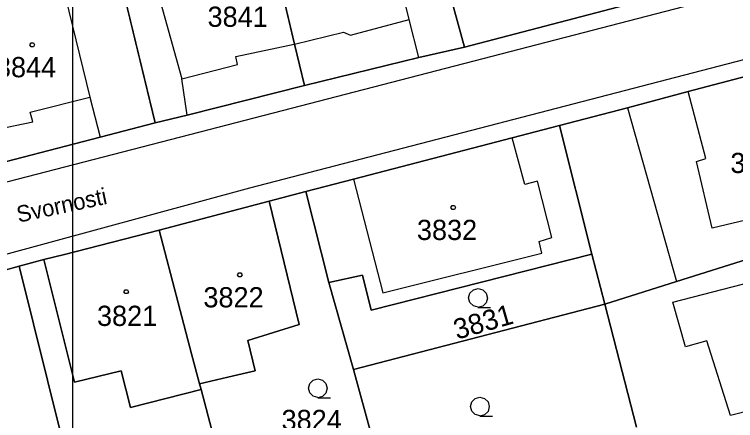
# Model space of a CAD drawing. Extents: x -263587 to -261993, y -1238795 to -1236748.
# Drawn here: x -262699.6 to -262642.6, y -1238145.4 to -1238113.2 of the extents above; entities that cross this region are included whole.
import ezdxf

# ---------------------------------------------------------------- set-up
doc = ezdxf.new("R2010")
doc.units = 0
doc.layers.add('Vrstva 1', color=7, linetype='Continuous')
doc.layers.add('Vrstva 51', color=7, linetype='Continuous')

msp = doc.modelspace()

# ---------------------------------------------------------------- linework, layer by layer
at = {"layer": 'Vrstva 1'}
for p, q in [((-262667.65, -1238102.68), (-262664.03, -1238115.82)), ((-262664.03, -1238115.82), (-262667.65, -1238102.68)), ((-262668.4, -1238113.62), (-262670.37, -1238105.54)), ((-262679.59, -1238106.68), (-262677.47, -1238115.57)), ((-262677.47, -1238115.57), (-262679.59, -1238106.68)), ((-262639.75, -1238109.44), (-262664.03, -1238115.82)), ((-262664.03, -1238115.82), (-262639.75, -1238109.44)), ((-262696.04, -1238109.96), (-262693.65, -1238119.78)), ((-262688.75, -1238109.85), (-262686.39, -1238118.33)), ((-262691.22, -1238110.44), (-262688.49, -1238121.81)), ((-262688.49, -1238121.81), (-262691.22, -1238110.44)), ((-262639.39, -1238110.71), (-262684.26, -1238122.35)), ((-262673.04, -1238114.87), (-262668.4, -1238113.62)), ((-262667.64, -1238116.63), (-262668.4, -1238113.62)), ((-262677.47, -1238115.57), (-262673.61, -1238114.64)), ((-262673.61, -1238114.64), (-262673.04, -1238114.87)), ((-262682.12, -1238116.57), (-262677.49, -1238115.57)), ((-262681.02, -1238126.95), (-262637.94, -1238115.76)), ((-262677.49, -1238115.57), (-262677.47, -1238115.57)), ((-262677.47, -1238115.57), (-262676.68, -1238118.85)), ((-262676.68, -1238118.85), (-262677.47, -1238115.57)), ((-262664.03, -1238115.82), (-262667.64, -1238116.63)), ((-262667.64, -1238116.63), (-262664.03, -1238115.82)), ((-262681.98, -1238117.19), (-262682.12, -1238116.57)), ((-262667.64, -1238116.63), (-262676.68, -1238118.85)), ((-262676.68, -1238118.85), (-262667.64, -1238116.63)), ((-262646.35, -1238119.34), (-262637.56, -1238117.01)), ((-262637.56, -1238117.01), (-262646.35, -1238119.34)), ((-262686.39, -1238118.33), (-262681.98, -1238117.19)), ((-262685.95, -1238121.19), (-262686.39, -1238118.33)), ((-262676.68, -1238118.85), (-262685.95, -1238121.19)), ((-262685.95, -1238121.19), (-262676.68, -1238118.85)), ((-262651.15, -1238120.61), (-262646.35, -1238119.34)), ((-262646.35, -1238119.34), (-262651.15, -1238120.61)), ((-262644.95, -1238124.63), (-262646.35, -1238119.34)), ((-262698.36, -1238120.95), (-262693.65, -1238119.78)), ((-262693.65, -1238119.78), (-262692.84, -1238122.94)), ((-262698.17, -1238121.72), (-262698.36, -1238120.95)), ((-262656.54, -1238122.03), (-262651.15, -1238120.61)), ((-262651.15, -1238120.61), (-262656.54, -1238122.03)), ((-262651.15, -1238120.61), (-262647.28, -1238134.37)), ((-262702.3, -1238122.58), (-262698.17, -1238121.72)), ((-262685.95, -1238121.19), (-262688.49, -1238121.81)), ((-262688.49, -1238121.81), (-262685.95, -1238121.19)), ((-262688.49, -1238121.81), (-262692.84, -1238122.94)), ((-262692.84, -1238122.94), (-262688.49, -1238121.81)), ((-262660.27, -1238123), (-262656.54, -1238122.03)), ((-262656.54, -1238122.03), (-262660.27, -1238123)), ((-262656.54, -1238122.03), (-262653.97, -1238132.2)), ((-262653.97, -1238132.2), (-262656.54, -1238122.03)), ((-262684.26, -1238122.35), (-262711.68, -1238129.45)), ((-262692.84, -1238122.94), (-262701.59, -1238125.22)), ((-262701.59, -1238125.22), (-262692.84, -1238122.94)), ((-262672.8, -1238126.27), (-262660.27, -1238123)), ((-262660.27, -1238123), (-262672.8, -1238126.27)), ((-262659.26, -1238126.68), (-262660.27, -1238123)), ((-262645.69, -1238124.86), (-262644.95, -1238124.63)), ((-262644.45, -1238130.14), (-262645.69, -1238124.86)), ((-262676.58, -1238127.25), (-262672.8, -1238126.27)), ((-262672.8, -1238126.27), (-262676.58, -1238127.25)), ((-262672.8, -1238126.27), (-262670.5, -1238135.27)), ((-262658.28, -1238126.42), (-262659.26, -1238126.68)), ((-262657.14, -1238130.89), (-262658.28, -1238126.42)), ((-262715.02, -1238136.22), (-262681.02, -1238126.95)), ((-262676.58, -1238127.25), (-262679.48, -1238128)), ((-262679.48, -1238128), (-262676.58, -1238127.25)), ((-262674.77, -1238134.44), (-262676.58, -1238127.25)), ((-262676.58, -1238127.25), (-262674.77, -1238134.44)), ((-262679.48, -1238128), (-262688.17, -1238130.3)), ((-262688.17, -1238130.3), (-262679.48, -1238128)), ((-262677.11, -1238137.76), (-262679.48, -1238128)), ((-262679.48, -1238128), (-262677.11, -1238137.76)), ((-262635.72, -1238128.03), (-262644.45, -1238130.14)), ((-262632.98, -1238129.87), (-262647.28, -1238134.37)), ((-262647.28, -1238134.37), (-262632.98, -1238129.87)), ((-262688.17, -1238130.3), (-262695.65, -1238132.22)), ((-262695.65, -1238132.22), (-262688.17, -1238130.3)), ((-262688.17, -1238130.3), (-262686.67, -1238136.06)), ((-262686.67, -1238136.06), (-262688.17, -1238130.3)), ((-262658.13, -1238131.19), (-262657.14, -1238130.89)), ((-262657.92, -1238132.11), (-262658.13, -1238131.19)), ((-262695.65, -1238132.22), (-262697.28, -1238132.63)), ((-262697.28, -1238132.63), (-262695.65, -1238132.22)), ((-262653.97, -1238132.2), (-262671.41, -1238136.62)), ((-262671.41, -1238136.62), (-262653.97, -1238132.2)), ((-262670.5, -1238135.27), (-262657.92, -1238132.11)), ((-262653.97, -1238132.2), (-262652.95, -1238136.16)), ((-262652.95, -1238136.16), (-262653.97, -1238132.2)), ((-262697.28, -1238132.63), (-262699.25, -1238133.16)), ((-262699.25, -1238133.16), (-262697.28, -1238132.63)), ((-262697.28, -1238132.63), (-262694.87, -1238142.34)), ((-262694.87, -1238142.34), (-262697.28, -1238132.63)), ((-262647.58, -1238136.01), (-262634.71, -1238132.65)), ((-262702.22, -1238133.98), (-262699.25, -1238133.16)), ((-262699.25, -1238133.16), (-262702.22, -1238133.98)), ((-262699.25, -1238133.16), (-262695.66, -1238147.61)), ((-262695.66, -1238147.61), (-262699.25, -1238133.16)), ((-262672.11, -1238133.86), (-262674.77, -1238134.44)), ((-262674.77, -1238134.44), (-262672.11, -1238133.86)), ((-262671.41, -1238136.62), (-262672.11, -1238133.86)), ((-262672.11, -1238133.86), (-262671.41, -1238136.62)), ((-262672.81, -1238141.32), (-262674.77, -1238134.44)), ((-262674.77, -1238134.44), (-262672.81, -1238141.32)), ((-262647.28, -1238134.37), (-262652.95, -1238136.16)), ((-262652.95, -1238136.16), (-262647.28, -1238134.37)), ((-262686.67, -1238136.06), (-262685.62, -1238140.09)), ((-262685.62, -1238140.09), (-262686.67, -1238136.06)), ((-262652.95, -1238136.16), (-262672.81, -1238141.32)), ((-262672.81, -1238141.32), (-262652.95, -1238136.16)), ((-262652.95, -1238136.16), (-262650.43, -1238145.89)), ((-262650.43, -1238145.89), (-262652.95, -1238136.16)), ((-262646.57, -1238139.53), (-262647.58, -1238136.01)), ((-262681.17, -1238139.02), (-262677.11, -1238137.76)), ((-262677.11, -1238137.76), (-262681.17, -1238139.02)), ((-262680.58, -1238141.42), (-262681.17, -1238139.02)), ((-262681.17, -1238139.02), (-262680.58, -1238141.42)), ((-262644.89, -1238139.05), (-262646.57, -1238139.53)), ((-262643, -1238144.96), (-262644.89, -1238139.05)), ((-262685.62, -1238140.09), (-262684.99, -1238142.45)), ((-262684.99, -1238142.45), (-262685.62, -1238140.09)), ((-262694.87, -1238142.34), (-262691.19, -1238141.44)), ((-262691.19, -1238141.44), (-262694.87, -1238142.34)), ((-262691.19, -1238141.44), (-262690.45, -1238144.33)), ((-262690.45, -1238144.33), (-262691.19, -1238141.44)), ((-262682.29, -1238141.82), (-262680.58, -1238141.42)), ((-262680.58, -1238141.42), (-262682.29, -1238141.82)), ((-262670.75, -1238148.86), (-262672.81, -1238141.32)), ((-262672.81, -1238141.32), (-262670.75, -1238148.86)), ((-262684.99, -1238142.45), (-262682.29, -1238141.82)), ((-262682.29, -1238141.82), (-262684.99, -1238142.45)), ((-262632.61, -1238142.25), (-262643, -1238144.96)), ((-262684.99, -1238142.45), (-262684.86, -1238142.92)), ((-262684.86, -1238142.92), (-262684.99, -1238142.45)), ((-262690.45, -1238144.33), (-262684.86, -1238142.92)), ((-262684.86, -1238142.92), (-262690.45, -1238144.33)), ((-262684.86, -1238142.92), (-262683.9, -1238146.52)), ((-262683.9, -1238146.52), (-262684.86, -1238142.92))]:
    msp.add_line(p, q, dxfattribs=at)
for points in [[(-262698.12, -1238115.48), (-262698.03, -1238115.63), (-262698.12, -1238115.78), (-262698.3, -1238115.78), (-262698.39, -1238115.63), (-262698.3, -1238115.48)], [(-262664.84, -1238128.36), (-262664.75, -1238128.51), (-262664.84, -1238128.66), (-262665.02, -1238128.66), (-262665.11, -1238128.51), (-262665.02, -1238128.36)], [(-262681.71, -1238133.69), (-262681.62, -1238133.84), (-262681.71, -1238133.99), (-262681.89, -1238133.99), (-262681.98, -1238133.84), (-262681.89, -1238133.69)], [(-262690.69, -1238135.02), (-262690.6, -1238135.17), (-262690.69, -1238135.32), (-262690.87, -1238135.32), (-262690.96, -1238135.17), (-262690.87, -1238135.02)]]:
    msp.add_lwpolyline(points, close=True, dxfattribs=at)
for points in [[(-262662.96, -1238136.4), (-262663.34, -1238136.3), (-262663.61, -1238136.03), (-262663.71, -1238135.66), (-262663.61, -1238135.29), (-262663.34, -1238135.02), (-262662.97, -1238134.92), (-262662.6, -1238135.02), (-262662.33, -1238135.29), (-262662.23, -1238135.67), (-262662.33, -1238136.05), (-262662.6, -1238136.32), (-262662.98, -1238136.42), (-262661.98, -1238136.42)], [(-262675.62, -1238143.54), (-262676, -1238143.44), (-262676.27, -1238143.17), (-262676.37, -1238142.8), (-262676.27, -1238142.43), (-262676, -1238142.16), (-262675.63, -1238142.06), (-262675.26, -1238142.16), (-262674.99, -1238142.43), (-262674.89, -1238142.81), (-262674.99, -1238143.19), (-262675.26, -1238143.46), (-262675.64, -1238143.56), (-262674.64, -1238143.56)], [(-262662.81, -1238144.99), (-262663.19, -1238144.89), (-262663.46, -1238144.62), (-262663.56, -1238144.25), (-262663.46, -1238143.88), (-262663.19, -1238143.61), (-262662.82, -1238143.51), (-262662.45, -1238143.61), (-262662.18, -1238143.88), (-262662.08, -1238144.26), (-262662.18, -1238144.64), (-262662.45, -1238144.91), (-262662.83, -1238145.01), (-262661.83, -1238145.01)]]:
    msp.add_lwpolyline(points, dxfattribs=at)
at = {"layer": 'Vrstva 51'}
msp.add_lwpolyline([(-262992.03, -1237088.09), (-262695.03, -1237088.09), (-262695.03, -1238768.09), (-262992.03, -1238768.09)], close=True, dxfattribs=at)

# ---------------------------------------------------------------- texts
at = {"layer": 'Vrstva 1'}
for s, p in [('3841', (-262684.349, -1238114.21)), ('3844', (-262701.078, -1238118.2)), ('3833', (-262643.018, -1238125.78)), ('3832', (-262667.798, -1238131.08)), ('3822', (-262684.678, -1238136.41)), ('3821', (-262693.089, -1238137.88)), ('3824', (-262678.498, -1238146.12))]:
    msp.add_text(s, height=1.6, dxfattribs=at).set_placement(p)
for s, height, rotation, p in [('Svornosti', 1.3, 11.9748, (-262699.292, -1238129.712)), ('3831', 1.6, 15.9855, (-262664.635, -1238138.974))]:
    msp.add_text(s, height=height, rotation=rotation, dxfattribs=at).set_placement(p)

doc.saveas('drawing.dxf')
